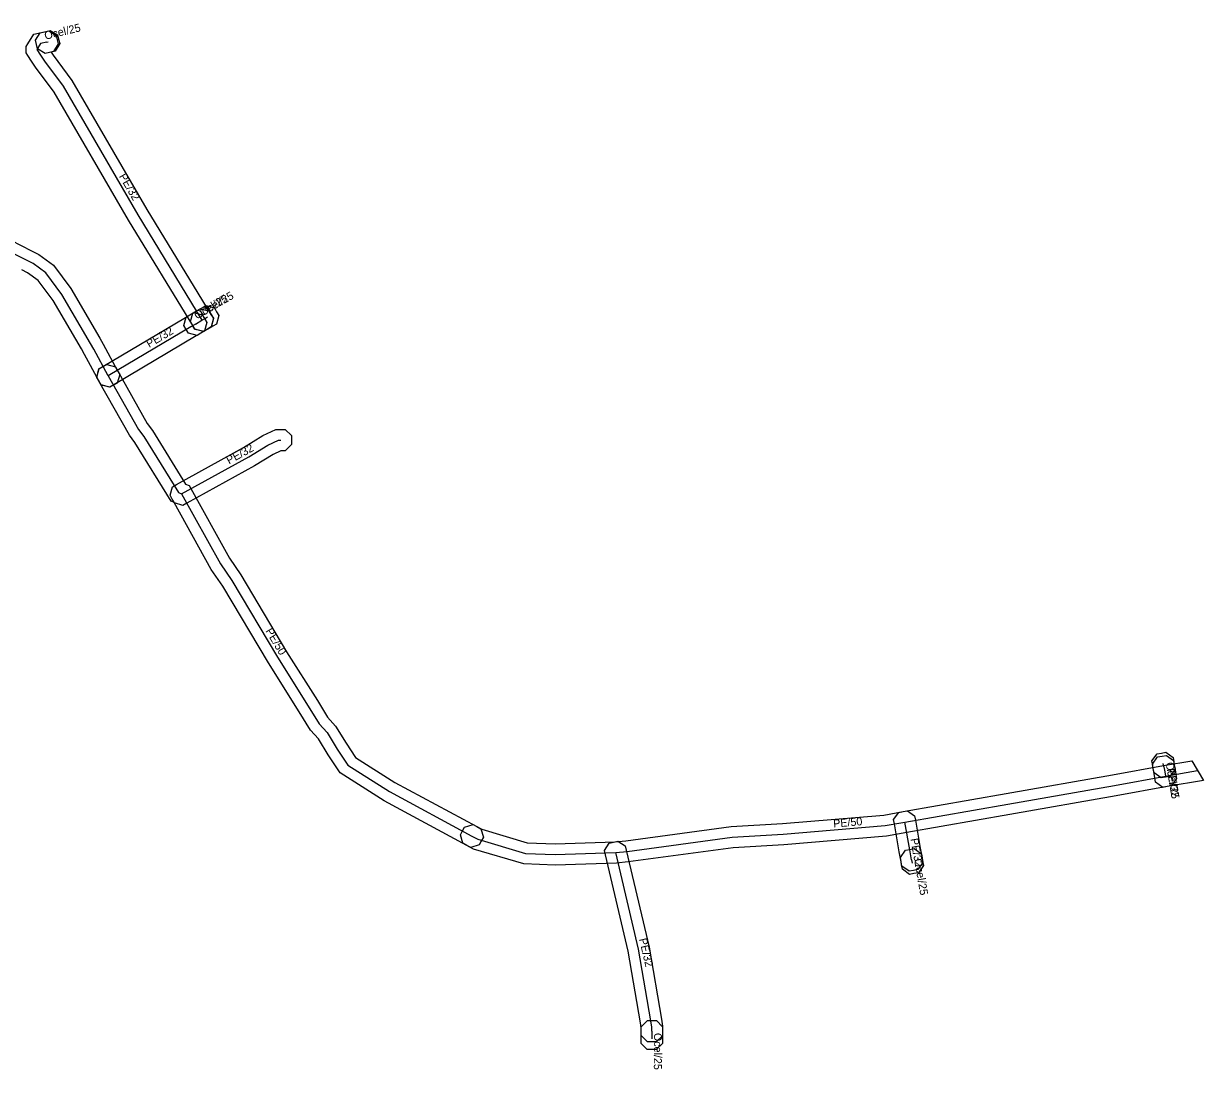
# Model space of a CAD drawing. Extents: x -677728 to -676939, y -1057290 to -1056960.
# Drawn here: x -677049.4 to -676938.8, y -1057057.8 to -1056959.8 of the extents above; entities that cross this region are included whole.
import ezdxf

# ---------------------------------------------------------------- set-up
doc = ezdxf.new("R2010")
doc.units = 0
for name, color, linetype in [('1', 7, 'Continuous'), ('24', 7, 'Continuous'), ('30', 7, 'Continuous')]:
    doc.layers.add(name, color=color, linetype=linetype)

msp = doc.modelspace()

# ---------------------------------------------------------------- linework, layer by layer
at = {"layer": '1'}
for points in [[(-677046.54, -1056962.42), (-677046.77, -1056962.47), (-677046.59, -1056962.75), (-677044.82, -1056965.13), (-677037.79, -1056977.22), (-677031.79, -1056987.07), (-677031.57, -1056987.42), (-677031.77, -1056988.23), (-677032.12, -1056988.44), (-677032.47, -1056988.66), (-677033.28, -1056988.46), (-677033.49, -1056988.11), (-677039.51, -1056978.24), (-677046.5, -1056966.23), (-677048.23, -1056963.9), (-677048.61, -1056963.33), (-677048.96, -1056962.79), (-677049.13, -1056962.54), (-677049.13, -1056961.95), (-677048.97, -1056961.7), (-677048.39, -1056960.8), (-677047.41, -1056960.57), (-677047, -1056960.47), (-677046.3, -1056960.91), (-677046.2, -1056961.31), (-677046.11, -1056961.71)], [(-677047.81, -1056960.66), (-677047.41, -1056960.57), (-677047.28, -1056960.53), (-677046.87, -1056960.44), (-677046.17, -1056960.87), (-677046.07, -1056961.27), (-677045.97, -1056961.68), (-677046.41, -1056962.38), (-677046.81, -1056962.48), (-677046.94, -1056962.51), (-677047.34, -1056962.61), (-677048.05, -1056962.18), (-677048.15, -1056961.77), (-677048.24, -1056961.37)], [(-677032.39, -1056988.6), (-677032.74, -1056988.81), (-677033.17, -1056989.07), (-677040.91, -1056993.67), (-677041.27, -1056993.88), (-677042.07, -1056993.68), (-677042.28, -1056993.32), (-677042.49, -1056992.97), (-677042.29, -1056992.16), (-677041.93, -1056991.95), (-677034.19, -1056987.35), (-677033.77, -1056987.1), (-677033.41, -1056986.88), (-677032.61, -1056987.09), (-677032.4, -1056987.44), (-677032.18, -1056987.8)], [(-677034.12, -1056987.31), (-677033.77, -1056987.09), (-677033.15, -1056986.73), (-677032.8, -1056986.52), (-677031.99, -1056986.72), (-677031.78, -1056987.08), (-677031.57, -1056987.44), (-677031.77, -1056988.24), (-677032.13, -1056988.45), (-677032.74, -1056988.81), (-677033.1, -1056989.03), (-677033.9, -1056988.82), (-677034.11, -1056988.47), (-677034.33, -1056988.11)], [(-677033.5, -1056986.93), (-677033.14, -1056986.72), (-677032.81, -1056986.53), (-677032.62, -1056986.43), (-677032.26, -1056986.22), (-677031.46, -1056986.44), (-677031.26, -1056986.8), (-677031.05, -1056987.16), (-677031.27, -1056987.96), (-677031.63, -1056988.16), (-677031.81, -1056988.27), (-677032.14, -1056988.46), (-677032.5, -1056988.66), (-677033.3, -1056988.45), (-677033.51, -1056988.09), (-677033.71, -1056987.73)], [(-677031.76, -1057010.95), (-677035.24, -1057004.68), (-677035.52, -1057004.57), (-677038.92, -1056999.07), (-677039.44, -1056998.38), (-677042.29, -1056993.3), (-677042.49, -1056992.94), (-677042.27, -1056992.14), (-677041.91, -1056991.94), (-677041.55, -1056991.74), (-677040.75, -1056991.96), (-677040.55, -1056992.32), (-677037.76, -1056997.28), (-677037.26, -1056997.95), (-677034.18, -1057002.95), (-677033.84, -1057003.08), (-677030.06, -1057009.9), (-677029, -1057011.45), (-677024.71, -1057018.67), (-677021.82, -1057023.25), (-677020.86, -1057024.81), (-677020.11, -1057025.64), (-677019.11, -1057027.25), (-677018.25, -1057028.57), (-677014.56, -1057030.92), (-677006.86, -1057035.06), (-677006.49, -1057035.25), (-677006.26, -1057036.05), (-677006.45, -1057036.41), (-677006.65, -1057036.78), (-677007.44, -1057037.02), (-677007.81, -1057036.82), (-677015.57, -1057032.64), (-677019.69, -1057030.03), (-677020.81, -1057028.33), (-677021.71, -1057026.84), (-677022.46, -1057026.02), (-677023.52, -1057024.31), (-677026.41, -1057019.71), (-677030.68, -1057012.53)], [(-677024.84, -1056999.83), (-677025.24, -1056999.83), (-677025.97, -1057000.18), (-677027.72, -1057001.26), (-677034.06, -1057004.76), (-677034.42, -1057004.96), (-677035.22, -1057004.73), (-677035.42, -1057004.36), (-677035.62, -1057004), (-677035.39, -1057003.2), (-677035.02, -1057003), (-677028.73, -1056999.54), (-677026.93, -1056998.42), (-677025.7, -1056997.83), (-677025.25, -1056997.83), (-677024.84, -1056997.83), (-677024.25, -1056998.42), (-677024.25, -1056998.83), (-677024.25, -1056999.24)], [(-676943.39, -1057030.01), (-676943.46, -1057029.6), (-676943.51, -1057029.31), (-676943.58, -1057028.9), (-676943.1, -1057028.23), (-676942.69, -1057028.16), (-676942.28, -1057028.09), (-676941.61, -1057028.57), (-676941.54, -1057028.98), (-676941.49, -1057029.27), (-676941.42, -1057029.68), (-676941.9, -1057030.35), (-676942.31, -1057030.42), (-676942.72, -1057030.49)], [(-676939.84, -1057028.89), (-676938.76, -1057030.73), (-676942.15, -1057031.31), (-676946.93, -1057032.18), (-676956.91, -1057033.93), (-676966.57, -1057035.62), (-676968.46, -1057035.95), (-676978.09, -1057036.76), (-676982.84, -1057037.04), (-676992.67, -1057038.37), (-676993.77, -1057038.48), (-676999.54, -1057038.66), (-677002.46, -1057038.56), (-677007.17, -1057037.16), (-677007.81, -1057036.82), (-677008.17, -1057036.62), (-677008.41, -1057035.83), (-677008.21, -1057035.46), (-677008.02, -1057035.1), (-677007.22, -1057034.86), (-677006.86, -1057035.06), (-677006.41, -1057035.3), (-677002.14, -1057036.57), (-676999.54, -1057036.66), (-676993.89, -1057036.48), (-676992.9, -1057036.39), (-676983.04, -1057035.04), (-676978.23, -1057034.76), (-676968.72, -1057033.97), (-676966.91, -1057033.65), (-676957.25, -1057031.96), (-676947.29, -1057030.22), (-676942.5, -1057029.34)], [(-676941.56, -1057028.86), (-676941.49, -1057029.27), (-676941.41, -1057029.75), (-676941.34, -1057030.16), (-676941.27, -1057030.56), (-676941.74, -1057031.24), (-676942.15, -1057031.31), (-676942.56, -1057031.38), (-676943.24, -1057030.9), (-676943.31, -1057030.49), (-676943.38, -1057030.08), (-676943.46, -1057029.61), (-676943.53, -1057029.2), (-676943.05, -1057028.52), (-676942.64, -1057028.45), (-676942.23, -1057028.38)], [(-676967.03, -1057038.76), (-676967.1, -1057038.35), (-676967.27, -1057037.41), (-676967.72, -1057034.81), (-676967.8, -1057034.4), (-676967.32, -1057033.72), (-676966.91, -1057033.65), (-676966.5, -1057033.58), (-676965.83, -1057034.05), (-676965.75, -1057034.46), (-676965.3, -1057037.07), (-676965.13, -1057038.01), (-676965.06, -1057038.42), (-676965.54, -1057039.09), (-676965.94, -1057039.17), (-676966.35, -1057039.24)], [(-676991.46, -1057054.64), (-676991.46, -1057054.22), (-676991.46, -1057053.92), (-676991.54, -1057053.44), (-676992.68, -1057046.74), (-676994.8, -1057037.71), (-676994.9, -1057037.31), (-676994.46, -1057036.6), (-676994.06, -1057036.51), (-676993.66, -1057036.41), (-676992.95, -1057036.85), (-676992.86, -1057037.25), (-676990.72, -1057046.34), (-676989.57, -1057053.1), (-676989.46, -1057053.76), (-676989.46, -1057054.23), (-676989.46, -1057054.65), (-676990.05, -1057055.23), (-676990.47, -1057055.23), (-676990.88, -1057055.23)], [(-676965.2, -1057037.6), (-676965.13, -1057038.01), (-676965.08, -1057038.3), (-676965.01, -1057038.71), (-676965.48, -1057039.39), (-676965.89, -1057039.46), (-676966.3, -1057039.53), (-676966.98, -1057039.05), (-676967.05, -1057038.65), (-676967.1, -1057038.35), (-676967.17, -1057037.95), (-676966.7, -1057037.27), (-676966.29, -1057037.2), (-676965.88, -1057037.12)], [(-676989.46, -1057053.82), (-676989.46, -1057054.23), (-676989.47, -1057054.96), (-676989.47, -1057055.38), (-676990.06, -1057055.96), (-676990.47, -1057055.96), (-676990.89, -1057055.96), (-676991.47, -1057055.37), (-676991.47, -1057054.95), (-676991.46, -1057054.22), (-676991.46, -1057053.81), (-676990.87, -1057053.23), (-676990.46, -1057053.23), (-676990.04, -1057053.23)]]:
    msp.add_lwpolyline(points, close=True, dxfattribs=at)
msp.add_lwpolyline([(-677050.56, -1056980.09), (-677048.63, -1056981.09), (-677047.94, -1056981.43), (-677046.56, -1056982.45), (-677044.94, -1056984.64), (-677042.2, -1056989.29), (-677041.9, -1056989.83), (-677040.54, -1056992.33), (-677040.34, -1056992.7), (-677040.58, -1056993.49), (-677040.94, -1056993.69), (-677041.31, -1056993.89), (-677042.1, -1056993.65), (-677042.3, -1056993.29), (-677043.65, -1056990.8), (-677043.94, -1056990.29), (-677046.6, -1056985.74), (-677047.98, -1056983.89), (-677048.98, -1056983.15), (-677049.53, -1056982.87)], dxfattribs=at)
at = {"layer": '24'}
for points in [[(-677047.18, -1056961.54), (-677047.77, -1056961.68), (-677048.13, -1056962.24), (-677047.77, -1056962.77), (-677047.41, -1056963.32), (-677045.66, -1056965.68), (-677038.65, -1056977.73), (-677032.64, -1056987.59)], [(-677047.18, -1056961.54), (-677047.04, -1056961.51)], [(-677041.42, -1056992.81), (-677042.77, -1056990.32), (-677043.07, -1056989.79), (-677045.77, -1056985.19), (-677047.27, -1056983.17), (-677048.46, -1056982.29), (-677049.08, -1056981.98), (-677051.01, -1056980.99), (-677053.24, -1056979.91), (-677058.69, -1056977.33), (-677060.64, -1056976.6), (-677068.01, -1056974.37), (-677068.29, -1056974.29), (-677068.44, -1056974.24)], [(-677032.64, -1056987.59), (-677032.31, -1056987.4), (-677032.12, -1056987.29)], [(-677033.25, -1056987.96), (-677033.68, -1056988.21), (-677041.42, -1056992.81)], [(-677033.25, -1056987.96), (-677032.64, -1056987.59)], [(-677041.42, -1056992.81), (-677038.6, -1056997.83), (-677038.09, -1056998.51), (-677034.85, -1057003.76), (-677034.54, -1057003.88), (-677030.91, -1057010.42), (-677029.84, -1057011.99), (-677025.56, -1057019.19), (-677022.67, -1057023.78), (-677021.66, -1057025.42), (-677020.91, -1057026.24), (-677019.96, -1057027.79), (-677018.97, -1057029.3), (-677015.06, -1057031.78), (-677007.33, -1057035.94)], [(-677034.54, -1057003.88), (-677028.23, -1057000.4), (-677026.45, -1056999.3), (-677025.47, -1056998.83), (-677025.25, -1056998.83)], [(-676942.47, -1057029.44), (-676942.52, -1057029.15)], [(-677007.33, -1057035.94), (-677006.79, -1057036.23), (-677002.3, -1057037.57), (-676999.54, -1057037.66), (-676993.83, -1057037.48), (-676992.78, -1057037.38), (-676982.94, -1057036.04), (-676978.16, -1057035.76), (-676968.59, -1057034.96), (-676966.74, -1057034.64), (-676957.08, -1057032.94), (-676947.11, -1057031.2), (-676942.32, -1057030.32), (-676939.3, -1057029.81)], [(-676942.47, -1057029.44), (-676942.39, -1057029.92), (-676942.32, -1057030.32)], [(-676966.12, -1057038.18), (-676966.28, -1057037.24), (-676966.74, -1057034.64)], [(-676990.46, -1057054.23), (-676990.46, -1057053.84), (-676990.56, -1057053.27), (-676991.7, -1057046.54), (-676993.83, -1057037.48)], [(-676966.12, -1057038.18), (-676966.07, -1057038.47)], [(-676990.46, -1057054.23), (-676990.47, -1057054.96)]]:
    msp.add_lwpolyline(points, dxfattribs=at)

# ---------------------------------------------------------------- texts
at = {"layer": '30'}
for s, rotation, p in [('Ocel/25', 13.5283, (-677047.31, -1056961.32)), ('PE/32', 300.1884, (-677040.44, -1056974.11)), ('Ocel/25', 29.9315, (-677032.58, -1056987.24)), ('Ocel/25', 30.7299, (-677033.1, -1056987.55)), ('PE/32', 30.7324, (-677037.58, -1056990.21)), ('PE/32', 28.877, (-677030.1, -1057001.12)), ('PE/50', 300.7291, (-677026.71, -1057016.72)), ('Ocel/25', 279.5581, (-676942.3, -1057029.09)), ('PE/32', 279.7143, (-676942.2, -1057029.68)), ('PE/50', 4.779, (-676973.43, -1057035.15)), ('PE/32', 279.9503, (-676966.23, -1057036.21)), ('Ocel/25', 279.9406, (-676965.89, -1057038.13)), ('PE/32', 283.2299, (-676991.67, -1057045.6)), ('Ocel/25', 269.6861, (-676990.26, -1057054.39))]:
    msp.add_text(s, height=0.75, rotation=rotation, dxfattribs=at).set_placement(p)

doc.saveas('drawing.dxf')
